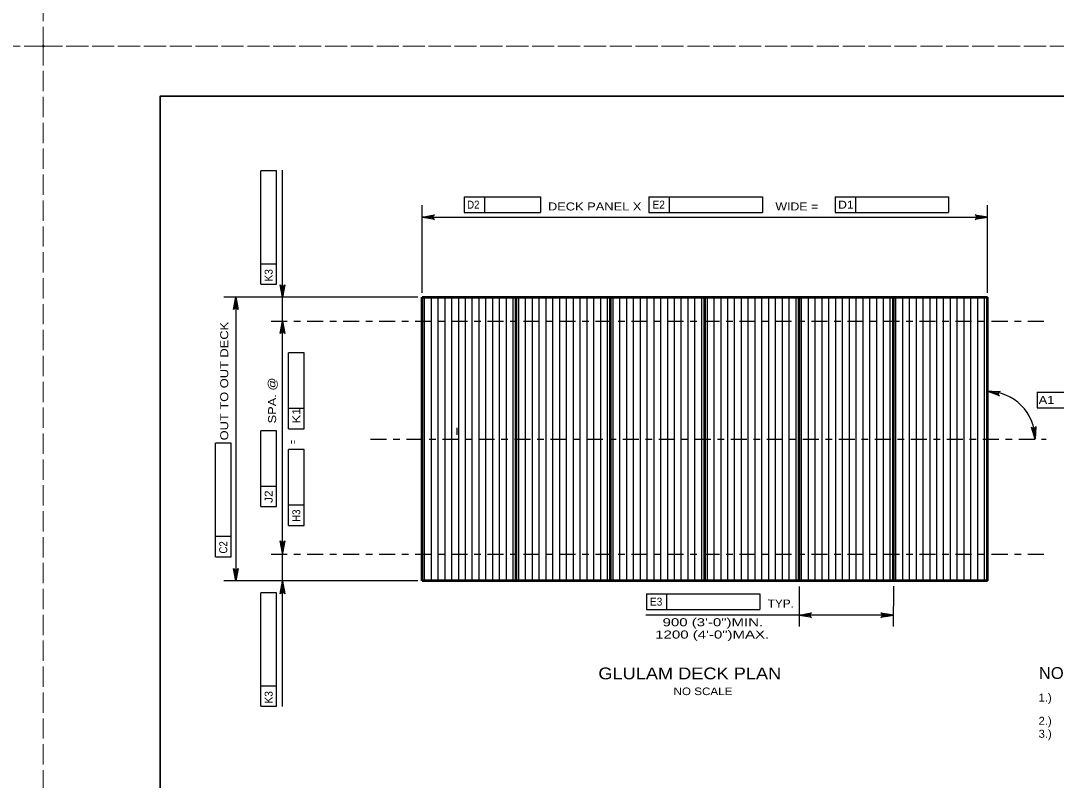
# Model space of a CAD drawing. Extents: x -11 to 79, y -154 to 0.
# Drawn here: x 33.66 to 49.19, y -99 to -87.62 of the extents above; entities that cross this region are included whole.
import ezdxf
from ezdxf.enums import TextEntityAlignment as Align

# ---------------------------------------------------------------- set-up
doc = ezdxf.new("R2010")
doc.units = 0
doc.header["$LTSCALE"] = 0.048
doc.header["$PDMODE"] = 32
doc.header["$PDSIZE"] = 0.024
doc.linetypes.add('DOT_DASHED', pattern=[7.7, 5, -1.2, 0.3, -1.2])
doc.linetypes.add('LONG_DASHED', pattern=[7.5, 6, -1.5])
for name, color, linetype, lineweight in [('1', 7, 'Continuous', 25), ('2', 7, 'Continuous', 35), ('4', 7, 'Continuous', 25), ('5', 7, 'Continuous', 25), ('63', 7, 'LONG_DASHED', 13)]:
    doc.layers.add(name, color=color, linetype=linetype, lineweight=lineweight)
doc.layers.add('62', color=7, linetype='Continuous')

msp = doc.modelspace()

# ---------------------------------------------------------------- hatches: boundary and pattern name
at = {"layer": '4'}
for points in [[(39.79758, -90.542), (39.79758, -90.582), (39.67758, -90.562)], [(48.03633, -90.542), (48.03633, -90.582), (48.15633, -90.562)], [(37.60842, -91.643), (37.56908, -91.643), (37.58875, -91.76117)], [(36.86533, -91.88117), (36.90533, -91.88117), (36.88533, -91.76117)], [(37.60842, -92.23792), (37.56908, -92.23792), (37.58875, -92.11983)], [(37.60842, -95.49267), (37.56908, -95.49267), (37.58875, -95.61075)], [(36.86533, -95.89308), (36.90533, -95.89308), (36.88533, -96.01308)], [(37.60842, -96.13117), (37.56908, -96.13117), (37.58875, -96.01308)], [(45.44342, -96.50583), (45.44342, -96.54367), (45.33, -96.52475)], [(46.62958, -96.50617), (46.62958, -96.54392), (46.743, -96.52508)]]:
    msp.add_hatch(color=256, dxfattribs=at).paths.add_polyline_path(points)

# ---------------------------------------------------------------- linework, layer by layer
at = {"layer": '1', "lineweight": 35}
msp.add_lwpolyline([(35.75, -109.25), (67.25, -109.25), (67.25, -88.75), (35.75, -88.75)], close=True, dxfattribs=at)
at = {"layer": '2', "lineweight": 53}
for p, q in [((39.67758, -91.76117), (48.15633, -91.76117)), ((39.67758, -96.01308), (39.67758, -91.76117)), ((41.09075, -96.01308), (41.09075, -91.76117)), ((42.50383, -96.01308), (42.50383, -91.76117)), ((43.917, -96.01308), (43.917, -91.76117)), ((45.33008, -96.01308), (45.33008, -91.76117)), ((46.74325, -96.01308), (46.74325, -91.76117)), ((48.15633, -96.01308), (48.15633, -91.76117)), ((48.15633, -96.01308), (39.67758, -96.01308))]:
    msp.add_line(p, q, dxfattribs=at)
at = {"layer": '2', "lineweight": 25}
msp.add_line((40.20208, -93.72117), (40.20208, -93.8245), dxfattribs=at)
at = {"layer": '4'}
for p, q in [((37.26042, -91.56767), (37.26042, -89.86692)), ((37.49667, -89.86717), (37.26042, -89.86692)), ((37.49667, -91.56792), (37.49667, -89.86717)), ((37.58875, -97.89642), (37.58875, -89.8575)), ((40.30958, -90.25708), (41.45617, -90.25708)), ((40.30958, -90.25708), (40.30958, -90.49325)), ((40.612, -90.25708), (40.612, -90.49325)), ((41.45617, -90.25708), (41.45617, -90.49325)), ((43.08042, -90.25708), (44.78117, -90.25708)), ((43.08042, -90.25708), (43.08042, -90.49325)), ((43.38283, -90.25708), (43.38283, -90.49325)), ((44.78117, -90.25708), (44.78117, -90.49325)), ((45.87183, -90.25708), (47.57258, -90.25708)), ((45.87183, -90.25708), (45.87183, -90.49325)), ((46.17425, -90.25708), (46.17425, -90.49325)), ((47.57258, -90.25708), (47.57258, -90.49325)), ((39.67758, -91.69867), (39.67758, -90.382)), ((40.30958, -90.49325), (41.45617, -90.49325)), ((43.08042, -90.49325), (44.78117, -90.49325)), ((45.87183, -90.49325), (47.57258, -90.49325)), ((48.15633, -91.69867), (48.15633, -90.382)), ((39.67758, -90.562), (48.15633, -90.562)), ((37.49667, -91.2655), (37.26042, -91.26525)), ((37.26042, -91.56767), (37.49667, -91.56792)), ((39.61508, -91.76117), (36.70533, -91.76117)), ((36.88533, -91.76117), (36.88533, -96.01308)), ((37.67483, -93.732), (37.67483, -92.59575)), ((37.91108, -92.596), (37.67483, -92.59575)), ((37.91108, -93.73225), (37.91108, -92.596)), ((48.89983, -93.183), (50.60067, -93.183)), ((48.89983, -93.183), (48.89983, -93.41925)), ((37.91108, -93.42975), (37.67483, -93.4295)), ((48.89983, -93.41925), (50.60067, -93.41925)), ((37.26042, -94.89883), (37.26042, -93.76258)), ((37.49667, -93.76283), (37.26042, -93.76258)), ((37.49667, -94.89908), (37.49667, -93.76283)), ((37.67483, -93.732), (37.91108, -93.73225)), ((36.57992, -95.65058), (36.57992, -93.94975)), ((36.81608, -93.95), (36.57992, -93.94975)), ((36.81608, -95.65083), (36.81608, -93.95)), ((37.67483, -95.18108), (37.67483, -94.04492)), ((37.91108, -94.04517), (37.67483, -94.04492)), ((37.91108, -95.18133), (37.91108, -94.04517)), ((37.49667, -94.59658), (37.26042, -94.59633)), ((37.26042, -94.89883), (37.49667, -94.89908)), ((37.91108, -94.87892), (37.67483, -94.87867)), ((37.67483, -95.18108), (37.91108, -95.18133)), ((36.81608, -95.34833), (36.57992, -95.34808)), ((36.57992, -95.65058), (36.81608, -95.65083)), ((39.61508, -96.01308), (36.70533, -96.01308)), ((46.74325, -96.09283), (46.74292, -96.69517)), ((37.26042, -97.89117), (37.26042, -96.19042)), ((37.49667, -96.19067), (37.26042, -96.19042)), ((37.49667, -97.89142), (37.49667, -96.19067)), ((43.04233, -96.20533), (44.74317, -96.20533)), ((43.04233, -96.20533), (43.04233, -96.44158)), ((43.34483, -96.20533), (43.34483, -96.44158)), ((44.74317, -96.20533), (44.74317, -96.44158)), ((45.33008, -96.096), (45.33, -96.69483)), ((46.743, -96.52508), (43.03492, -96.52425)), ((43.04233, -96.44158), (44.74317, -96.44158)), ((37.49667, -97.589), (37.26042, -97.58875)), ((37.26042, -97.89117), (37.49667, -97.89142))]:
    msp.add_line(p, q, dxfattribs=at)
at = {"layer": '4', "linetype": 'DOT_DASHED'}
for p, q in [((37.41733, -92.11983), (49.03208, -92.11983)), ((38.90625, -93.88708), (49.03208, -93.88708)), ((37.41733, -95.61075), (49.03208, -95.61075))]:
    msp.add_line(p, q, dxfattribs=at)
at = {"layer": '4'}
for points in [[(39.67758, -90.562), (39.864, -90.52708), (39.84967, -90.537), (39.84225, -90.5495), (39.84008, -90.562), (39.84225, -90.5745), (39.84967, -90.587), (39.864, -90.59692), (39.67758, -90.562), (39.84967, -90.587), (39.84225, -90.5745), (39.67758, -90.562), (39.84008, -90.562), (39.84225, -90.5495), (39.67758, -90.562), (39.84967, -90.537)], [(48.15633, -90.562), (47.96992, -90.59692), (47.98425, -90.587), (47.99167, -90.5745), (47.99383, -90.562), (47.99167, -90.5495), (47.98425, -90.537), (47.96992, -90.52708), (48.15633, -90.562), (47.98425, -90.537), (47.99167, -90.5495), (48.15633, -90.562), (47.99383, -90.562), (47.99167, -90.5745), (48.15633, -90.562), (47.98425, -90.587)], [(37.58875, -91.76117), (37.55383, -91.57475), (37.56375, -91.58908), (37.57625, -91.5965), (37.58875, -91.59867), (37.60125, -91.5965), (37.61375, -91.58908), (37.62367, -91.57475), (37.58875, -91.76117), (37.61375, -91.58908), (37.60125, -91.5965), (37.58875, -91.76117), (37.58875, -91.59867), (37.57625, -91.5965), (37.58875, -91.76117), (37.56375, -91.58908)], [(36.88533, -91.76117), (36.92025, -91.94758), (36.91033, -91.93325), (36.89783, -91.92583), (36.88533, -91.92367), (36.87283, -91.92583), (36.86033, -91.93325), (36.85042, -91.94758), (36.88533, -91.76117), (36.86033, -91.93325), (36.87283, -91.92583), (36.88533, -91.76117), (36.88533, -91.92367), (36.89783, -91.92583), (36.88533, -91.76117), (36.91033, -91.93325)], [(37.58875, -92.11983), (37.62367, -92.30625), (37.61375, -92.29192), (37.60125, -92.2845), (37.58875, -92.28233), (37.57625, -92.2845), (37.56375, -92.29192), (37.55383, -92.30625), (37.58875, -92.11983), (37.56375, -92.29192), (37.57625, -92.2845), (37.58875, -92.11983), (37.58875, -92.28233), (37.60125, -92.2845), (37.58875, -92.11983), (37.61375, -92.29192)], [(48.15658, -93.17083), (48.34625, -93.17267), (48.33025, -93.17967), (48.3205, -93.1905), (48.316, -93.20233), (48.31567, -93.215), (48.32058, -93.22875), (48.33267, -93.24125), (48.15658, -93.17083), (48.32058, -93.22875), (48.31567, -93.215), (48.15658, -93.17083), (48.316, -93.20233), (48.3205, -93.1905), (48.15658, -93.17083), (48.33025, -93.17967)], [(48.87042, -93.88708), (48.812, -93.70658), (48.82375, -93.71958), (48.83708, -93.72533), (48.84975, -93.72592), (48.86192, -93.72217), (48.87333, -93.71325), (48.88133, -93.69775), (48.87042, -93.88708), (48.87333, -93.71325), (48.86192, -93.72217), (48.87042, -93.88708), (48.84975, -93.72592), (48.83708, -93.72533), (48.87042, -93.88708), (48.82375, -93.71958)], [(37.58683, -95.59917), (37.55183, -95.41275), (37.56183, -95.42717), (37.57433, -95.43458), (37.58683, -95.43667), (37.59933, -95.43458), (37.61183, -95.42717), (37.62175, -95.41275), (37.58683, -95.59917), (37.61183, -95.42717), (37.59933, -95.43458), (37.58683, -95.59917), (37.58683, -95.43667), (37.57433, -95.43458), (37.58683, -95.59917), (37.56183, -95.42717)], [(36.88533, -96.01308), (36.85042, -95.82667), (36.86033, -95.841), (36.87283, -95.84842), (36.88533, -95.85058), (36.89783, -95.84842), (36.91033, -95.841), (36.92025, -95.82667), (36.88533, -96.01308), (36.91033, -95.841), (36.89783, -95.84842), (36.88533, -96.01308), (36.88533, -95.85058), (36.87283, -95.84842), (36.88533, -96.01308), (36.86033, -95.841)], [(37.58792, -96.01833), (37.62283, -96.20475), (37.61292, -96.19042), (37.60042, -96.183), (37.58792, -96.18083), (37.57542, -96.183), (37.56292, -96.19042), (37.55292, -96.20475), (37.58792, -96.01833), (37.56292, -96.19042), (37.57542, -96.183), (37.58792, -96.01833), (37.58792, -96.18083), (37.60042, -96.183), (37.58792, -96.01833), (37.61292, -96.19042)], [(45.32992, -96.52475), (45.51633, -96.48983), (45.50192, -96.49975), (45.49458, -96.51225), (45.49242, -96.52475), (45.49458, -96.53725), (45.50192, -96.54975), (45.51633, -96.55975), (45.32992, -96.52475), (45.50192, -96.54975), (45.49458, -96.53725), (45.32992, -96.52475), (45.49242, -96.52475), (45.49458, -96.51225), (45.32992, -96.52475), (45.50192, -96.49975)], [(46.743, -96.52508), (46.55658, -96.56), (46.571, -96.55008), (46.57833, -96.53758), (46.5805, -96.52508), (46.57833, -96.51258), (46.571, -96.50008), (46.55658, -96.49017), (46.743, -96.52508), (46.571, -96.50008), (46.57833, -96.51258), (46.743, -96.52508), (46.5805, -96.52508), (46.57833, -96.53758), (46.743, -96.52508), (46.571, -96.55008)]]:
    msp.add_lwpolyline(points, dxfattribs=at)
for points in [[(39.79758, -90.542), (39.79758, -90.582), (39.67758, -90.562)], [(48.03633, -90.542), (48.03633, -90.582), (48.15633, -90.562)], [(37.60842, -91.643), (37.56908, -91.643), (37.58875, -91.76117)], [(36.86533, -91.88117), (36.90533, -91.88117), (36.88533, -91.76117)], [(37.60842, -92.23792), (37.56908, -92.23792), (37.58875, -92.11983)], [(37.60842, -95.49267), (37.56908, -95.49267), (37.58875, -95.61075)], [(36.86533, -95.89308), (36.90533, -95.89308), (36.88533, -96.01308)], [(37.60842, -96.13117), (37.56908, -96.13117), (37.58875, -96.01308)], [(45.44342, -96.50583), (45.44342, -96.54367), (45.33, -96.52475)], [(46.62958, -96.50617), (46.62958, -96.54392), (46.743, -96.52508)]]:
    msp.add_lwpolyline(points, close=True, dxfattribs=at)
msp.add_arc((48.15634, -93.88711), 0.71404, 0.00231, 90.00265, dxfattribs=at)
at = {"layer": '5'}
for p, q in [((39.71592, -96.01308), (39.71592, -91.76117)), ((39.81825, -96.01308), (39.81825, -91.76117)), ((39.9205, -96.01308), (39.9205, -91.76117)), ((40.02275, -96.01308), (40.02275, -91.76117)), ((40.12508, -96.01308), (40.12508, -91.76117)), ((40.22733, -96.01308), (40.22733, -91.76117)), ((40.32967, -96.01308), (40.32967, -91.76117)), ((40.43192, -96.01308), (40.43192, -91.76117)), ((40.53425, -96.01308), (40.53425, -91.76117)), ((40.6365, -96.01308), (40.6365, -91.76117)), ((40.73875, -96.01308), (40.73875, -91.76117)), ((40.84108, -96.01308), (40.84108, -91.76117)), ((40.94333, -96.01308), (40.94333, -91.76117)), ((41.04567, -96.01308), (41.04567, -91.76117)), ((41.12908, -96.01308), (41.12908, -91.76117)), ((41.23133, -96.01308), (41.23133, -91.76117)), ((41.33358, -96.01308), (41.33358, -91.76117)), ((41.43592, -96.01308), (41.43592, -91.76117)), ((41.53817, -96.01308), (41.53817, -91.76117)), ((41.6405, -96.01308), (41.6405, -91.76117)), ((41.74275, -96.01308), (41.74275, -91.76117)), ((41.84508, -96.01308), (41.84508, -91.76117)), ((41.94733, -96.01308), (41.94733, -91.76117)), ((42.04967, -96.01308), (42.04967, -91.76117)), ((42.15192, -96.01308), (42.15192, -91.76117)), ((42.25417, -96.01308), (42.25417, -91.76117)), ((42.3565, -96.01308), (42.3565, -91.76117)), ((42.45875, -96.01308), (42.45875, -91.76117)), ((42.54217, -96.01308), (42.54217, -91.76117)), ((42.6445, -96.01308), (42.6445, -91.76117)), ((42.74675, -96.01308), (42.74675, -91.76117)), ((42.849, -96.01308), (42.849, -91.76117)), ((42.95133, -96.01308), (42.95133, -91.76117)), ((43.05358, -96.01308), (43.05358, -91.76117)), ((43.15592, -96.01308), (43.15592, -91.76117)), ((43.25817, -96.01308), (43.25817, -91.76117)), ((43.3605, -96.01308), (43.3605, -91.76117)), ((43.46275, -96.01308), (43.46275, -91.76117)), ((43.565, -96.01308), (43.565, -91.76117)), ((43.66733, -96.01308), (43.66733, -91.76117)), ((43.76958, -96.01308), (43.76958, -91.76117)), ((43.87192, -96.01308), (43.87192, -91.76117)), ((43.95533, -96.01308), (43.95533, -91.76117)), ((44.05758, -96.01308), (44.05758, -91.76117)), ((44.15983, -96.01308), (44.15983, -91.76117)), ((44.26217, -96.01308), (44.26217, -91.76117)), ((44.36442, -96.01308), (44.36442, -91.76117)), ((44.46675, -96.01308), (44.46675, -91.76117)), ((44.569, -96.01308), (44.569, -91.76117)), ((44.67133, -96.01308), (44.67133, -91.76117)), ((44.77358, -96.01308), (44.77358, -91.76117)), ((44.87592, -96.01308), (44.87592, -91.76117)), ((44.97817, -96.01308), (44.97817, -91.76117)), ((45.08042, -96.01308), (45.08042, -91.76117)), ((45.18275, -96.01308), (45.18275, -91.76117)), ((45.285, -96.01308), (45.285, -91.76117)), ((45.36842, -96.01308), (45.36842, -91.76117)), ((45.47075, -96.01308), (45.47075, -91.76117)), ((45.573, -96.01308), (45.573, -91.76117)), ((45.67525, -96.01308), (45.67525, -91.76117)), ((45.77758, -96.01308), (45.77758, -91.76117)), ((45.87983, -96.01308), (45.87983, -91.76117)), ((45.98217, -96.01308), (45.98217, -91.76117)), ((46.08442, -96.01308), (46.08442, -91.76117)), ((46.18675, -96.01308), (46.18675, -91.76117)), ((46.289, -96.01308), (46.289, -91.76117)), ((46.39125, -96.01308), (46.39125, -91.76117)), ((46.49358, -96.01308), (46.49358, -91.76117)), ((46.59583, -96.01308), (46.59583, -91.76117)), ((46.69817, -96.01308), (46.69817, -91.76117)), ((46.78158, -96.01308), (46.78158, -91.76117)), ((46.88383, -96.01308), (46.88383, -91.76117)), ((46.98608, -96.01308), (46.98608, -91.76117)), ((47.08842, -96.01308), (47.08842, -91.76117)), ((47.19067, -96.01308), (47.19067, -91.76117)), ((47.293, -96.01308), (47.293, -91.76117)), ((47.39525, -96.01308), (47.39525, -91.76117)), ((47.49758, -96.01308), (47.49758, -91.76117)), ((47.59983, -96.01308), (47.59983, -91.76117)), ((47.70217, -96.01308), (47.70217, -91.76117)), ((47.80442, -96.01308), (47.80442, -91.76117)), ((47.90667, -96.01308), (47.90667, -91.76117)), ((48.009, -96.01308), (48.009, -91.76117)), ((48.11125, -96.01308), (48.11125, -91.76117))]:
    msp.add_line(p, q, dxfattribs=at)
at = {"layer": '62'}
msp.add_point((34, -88), dxfattribs=at)
at = {"layer": '63'}
for points in [[(0, -88), (34, -88), (34, -66), (0, -66)], [(34, -88), (68, -88), (68, -66), (34, -66)], [(0, -110), (34, -110), (34, -88), (0, -88)], [(34, -110), (68, -110), (68, -88), (34, -88)]]:
    msp.add_lwpolyline(points, close=True, dxfattribs=at)

# ---------------------------------------------------------------- texts
at = {"layer": '4'}
for s, rotation, width, p in [('D2', 359.938, 0.9, (40.44594, -90.43518)), ('E2', 359.938, 0.95, (43.22502, -90.43518)), ('D1', 359.938, 1.15, (46.03185, -90.43521)), ('K3', 89.938, 0.95, (37.4386, -91.43373)), ('OUT TO OUT DECK', 90, 1.2, (36.77292, -93.019)), ('A1', 359.938, 1.2, (49.03935, -93.36113)), ('K1', 89.938, 1.2, (37.85305, -93.53573)), ('J2', 89.938, 1.1, (37.4386, -94.74998)), ('H3', 89.938, 0.9, (37.85302, -95.03556)), ('C2', 89.938, 0.9, (36.75802, -95.5104)), ('E3', 359.938, 0.95, (43.18694, -96.38352)), ('K3', 89.938, 0.95, (37.4386, -97.75723))]:
    msp.add_text(s, height=0.12, rotation=rotation, dxfattribs=dict(at, width=width)).set_placement(p, align=Align.CENTER)
for s, height, width, p in [('DECK PANEL X', 0.12, 1.2, (41.56533, -90.462)), ('WIDE =', 0.12, 1.15, (44.9755, -90.462)), ('NOTES:', 0.1772, 1.05, (48.924, -97.48167)), ('NO SCALE', 0.1134, 1.15, (43.44842, -97.72375)), ('1.)', 0.12, 1.05, (48.92058, -97.82092)), ('2.)', 0.12, 1.05, (48.92058, -98.169)), ('3.)', 0.12, 1.05, (48.92058, -98.36292))]:
    msp.add_text(s, height=height, dxfattribs=dict(at, width=width)).set_placement(p)
for s, rotation, width, p in [('SPA. @', 90, 1.2, (37.49067, -93.65325)), ('=', 90, 0.6, (37.79983, -93.96383)), ('TYP.', 359.938, 1.1, (44.86042, -96.41125))]:
    msp.add_text(s, height=0.12, rotation=rotation, dxfattribs=dict(at, width=width)).set_placement(p)
for s, height, width, p in [('900 (3\'-0")MIN.', 0.12, 1.4, (44.038, -96.692)), ('1200 (4\'-0")MAX.', 0.12, 1.4, (44.02788, -96.87608)), ('GLULAM DECK PLAN', 0.1772, 1.15, (43.69175, -97.48758))]:
    msp.add_text(s, height=height, dxfattribs=dict(at, width=width)).set_placement(p, align=Align.CENTER)

doc.saveas('drawing.dxf')
